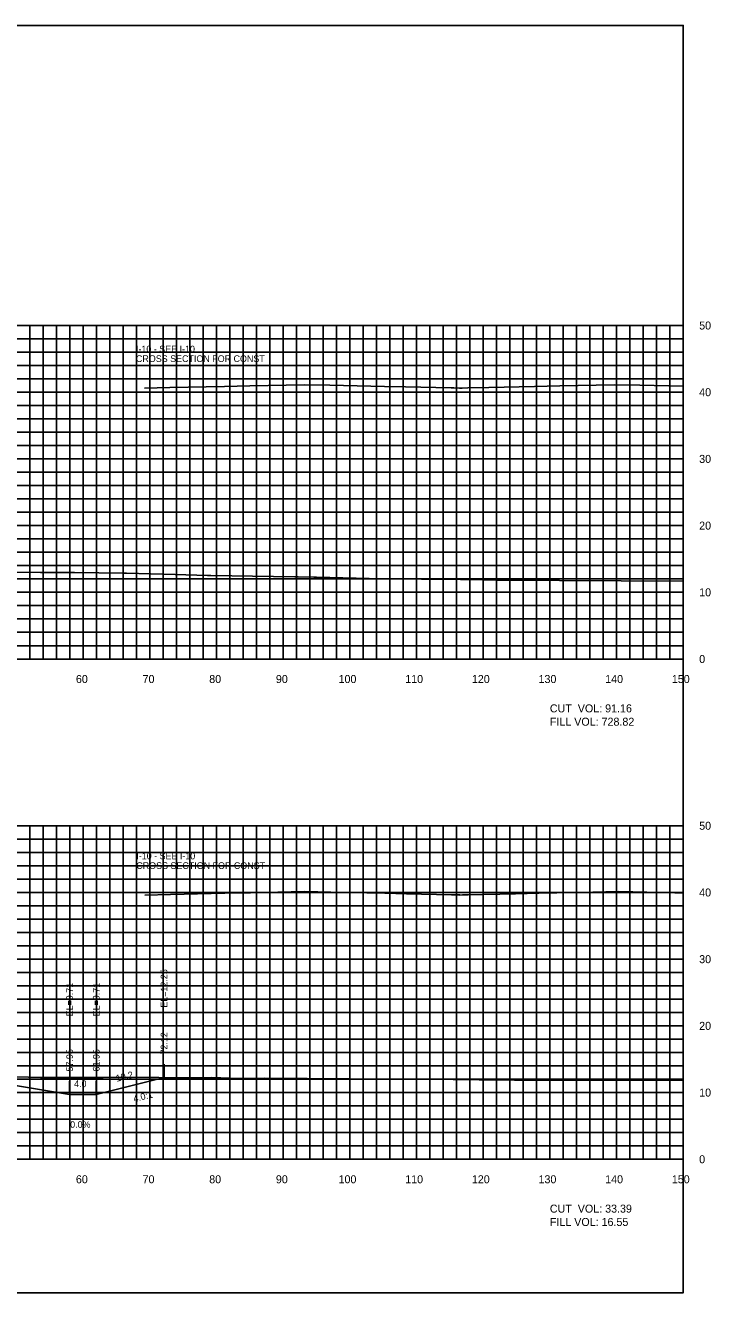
# Model space of a CAD drawing. Extents: x 1797714 to 1804825, y 249015 to 250269.
# Drawn here: x 1802682.3 to 1802785.1, y 250079.4 to 250269.4 of the extents above; entities that cross this region are included whole.
import ezdxf

# ---------------------------------------------------------------- set-up
doc = ezdxf.new("R2010")
doc.units = 0
for name, color, linetype in [('10', 7, 'Continuous'), ('3', 7, 'Continuous'), ('31', 7, 'Continuous'), ('4', 7, 'Continuous'), ('60', 7, 'Continuous'), ('ANNO-TXT', 7, 'Continuous'), ('CL-CNST', 7, 'Continuous'), ('Level 62', 7, 'Continuous'), ('M-ROADS', 7, 'Continuous')]:
    doc.layers.add(name, color=color, linetype=linetype)

msp = doc.modelspace()

# ---------------------------------------------------------------- linework, layer by layer
for p, q in [((1802703.12, 250111.68), (1802703.12, 250113.68)), ((1802688.95, 250109.14), (1802688.95, 250111.14)), ((1802692.95, 250109.14), (1802692.95, 250111.14))]:
    msp.add_line(p, q)
msp.add_lwpolyline([(1802481, 250079.43), (1802781, 250079.43), (1802781, 250269.43), (1802481, 250269.43)], close=True)
at = {"layer": '60'}
for p, q in [((1802781, 250174.43), (1802781, 250224.43)), ((1802781.06, 250224.43), (1802781, 250224.43)), ((1802781.06, 250214.43), (1802781, 250214.43)), ((1802781.06, 250204.43), (1802781, 250204.43)), ((1802781.06, 250194.43), (1802781, 250194.43)), ((1802781.06, 250184.43), (1802781, 250184.43)), ((1802481, 250174.43), (1802781, 250174.43)), ((1802691, 250174.37), (1802691, 250174.43)), ((1802701, 250174.37), (1802701, 250174.43)), ((1802711, 250174.37), (1802711, 250174.43)), ((1802721, 250174.37), (1802721, 250174.43)), ((1802731, 250174.37), (1802731, 250174.43)), ((1802741, 250174.37), (1802741, 250174.43)), ((1802751, 250174.37), (1802751, 250174.43)), ((1802761, 250174.37), (1802761, 250174.43)), ((1802771, 250174.37), (1802771, 250174.43)), ((1802781, 250174.37), (1802781, 250174.43)), ((1802781.06, 250174.43), (1802781, 250174.43)), ((1802781, 250099.43), (1802781, 250149.43)), ((1802781.06, 250149.43), (1802781, 250149.43)), ((1802781.06, 250139.43), (1802781, 250139.43)), ((1802781.06, 250129.43), (1802781, 250129.43)), ((1802781.06, 250119.43), (1802781, 250119.43)), ((1802781.06, 250109.43), (1802781, 250109.43)), ((1802481, 250099.43), (1802781, 250099.43)), ((1802691, 250099.37), (1802691, 250099.43)), ((1802701, 250099.37), (1802701, 250099.43)), ((1802711, 250099.37), (1802711, 250099.43)), ((1802721, 250099.37), (1802721, 250099.43)), ((1802731, 250099.37), (1802731, 250099.43)), ((1802741, 250099.37), (1802741, 250099.43)), ((1802751, 250099.37), (1802751, 250099.43)), ((1802761, 250099.37), (1802761, 250099.43)), ((1802771, 250099.37), (1802771, 250099.43)), ((1802781, 250099.37), (1802781, 250099.43)), ((1802781.06, 250099.43), (1802781, 250099.43))]:
    msp.add_line(p, q, dxfattribs=at)
at = {"layer": 'CL-CNST'}
for points in [[(1802700.2, 250215.03), (1802703.98, 250215.12), (1802712.2, 250215.3), (1802715.98, 250215.38), (1802724.2, 250215.56), (1802727.98, 250215.48), (1802736.2, 250215.3), (1802739.35, 250215.23), (1802746.2, 250215.08), (1802746.6, 250215.07), (1802747.45, 250215.05), (1802747.45, 250215.05), (1802747.45, 250215.05), (1802747.85, 250215.06), (1802748.7, 250215.08), (1802751.86, 250215.15), (1802758.7, 250215.3), (1802762.49, 250215.38), (1802770.7, 250215.56), (1802774.49, 250215.48), (1802781, 250215.33)], [(1802700.25, 250139.03), (1802704.11, 250139.12), (1802712.25, 250139.3), (1802716.11, 250139.38), (1802724.25, 250139.56), (1802728.12, 250139.48), (1802736.25, 250139.3), (1802739.47, 250139.23), (1802746.25, 250139.08), (1802746.65, 250139.07), (1802747.49, 250139.05), (1802747.49, 250139.05), (1802747.5, 250139.04), (1802747.9, 250139.05), (1802748.75, 250139.07), (1802755.83, 250139.22), (1802759.33, 250139.3), (1802767.45, 250139.48), (1802771.33, 250139.56), (1802779.76, 250139.38), (1802781, 250139.35)], [(1802608.84, 250113.01), (1802618.84, 250113.41), (1802631, 250113.63), (1802658, 250113.04), (1802662, 250112.88), (1802667.95, 250112.64), (1802688.95, 250109.14), (1802692.95, 250109.14), (1802703.12, 250111.68)]]:
    msp.add_lwpolyline(points, dxfattribs=at)
at = {"layer": 'Level 62'}
for p, q in [((1802481, 250224.43), (1802781, 250224.43)), ((1802683, 250174.43), (1802683, 250224.43)), ((1802685, 250174.43), (1802685, 250224.43)), ((1802687, 250174.43), (1802687, 250224.43)), ((1802689, 250174.43), (1802689, 250224.43)), ((1802691, 250174.43), (1802691, 250224.43)), ((1802693, 250174.43), (1802693, 250224.43)), ((1802695, 250174.43), (1802695, 250224.43)), ((1802697, 250174.43), (1802697, 250224.43)), ((1802699, 250174.43), (1802699, 250224.43)), ((1802701, 250174.43), (1802701, 250224.43)), ((1802703, 250174.43), (1802703, 250224.43)), ((1802705, 250174.43), (1802705, 250224.43)), ((1802707, 250174.43), (1802707, 250224.43)), ((1802709, 250174.43), (1802709, 250224.43)), ((1802711, 250174.43), (1802711, 250224.43)), ((1802713, 250174.43), (1802713, 250224.43)), ((1802715, 250174.43), (1802715, 250224.43)), ((1802717, 250174.43), (1802717, 250224.43)), ((1802719, 250174.43), (1802719, 250224.43)), ((1802721, 250174.43), (1802721, 250224.43)), ((1802723, 250174.43), (1802723, 250224.43)), ((1802725, 250174.43), (1802725, 250224.43)), ((1802727, 250174.43), (1802727, 250224.43)), ((1802729, 250174.43), (1802729, 250224.43)), ((1802731, 250174.43), (1802731, 250224.43)), ((1802733, 250174.43), (1802733, 250224.43)), ((1802735, 250174.43), (1802735, 250224.43)), ((1802737, 250174.43), (1802737, 250224.43)), ((1802739, 250174.43), (1802739, 250224.43)), ((1802741, 250174.43), (1802741, 250224.43)), ((1802743, 250174.43), (1802743, 250224.43)), ((1802745, 250174.43), (1802745, 250224.43)), ((1802747, 250174.43), (1802747, 250224.43)), ((1802749, 250174.43), (1802749, 250224.43)), ((1802751, 250174.43), (1802751, 250224.43)), ((1802753, 250174.43), (1802753, 250224.43)), ((1802755, 250174.43), (1802755, 250224.43)), ((1802757, 250174.43), (1802757, 250224.43)), ((1802759, 250174.43), (1802759, 250224.43)), ((1802761, 250174.43), (1802761, 250224.43)), ((1802763, 250174.43), (1802763, 250224.43)), ((1802765, 250174.43), (1802765, 250224.43)), ((1802767, 250174.43), (1802767, 250224.43)), ((1802769, 250174.43), (1802769, 250224.43)), ((1802771, 250174.43), (1802771, 250224.43)), ((1802773, 250174.43), (1802773, 250224.43)), ((1802775, 250174.43), (1802775, 250224.43)), ((1802777, 250174.43), (1802777, 250224.43)), ((1802779, 250174.43), (1802779, 250224.43)), ((1802781, 250174.43), (1802781, 250224.43)), ((1802481, 250222.43), (1802781, 250222.43)), ((1802481, 250220.43), (1802781, 250220.43)), ((1802481, 250218.43), (1802781, 250218.43)), ((1802481, 250216.43), (1802781, 250216.43)), ((1802481, 250214.43), (1802781, 250214.43)), ((1802481, 250212.43), (1802781, 250212.43)), ((1802481, 250210.43), (1802781, 250210.43)), ((1802481, 250208.43), (1802781, 250208.43)), ((1802481, 250206.43), (1802781, 250206.43)), ((1802481, 250204.43), (1802781, 250204.43)), ((1802481, 250202.43), (1802781, 250202.43)), ((1802481, 250200.43), (1802781, 250200.43)), ((1802481, 250198.43), (1802781, 250198.43)), ((1802481, 250196.43), (1802781, 250196.43)), ((1802481, 250194.43), (1802781, 250194.43)), ((1802481, 250192.43), (1802781, 250192.43)), ((1802481, 250190.43), (1802781, 250190.43)), ((1802481, 250188.43), (1802781, 250188.43)), ((1802481, 250186.43), (1802781, 250186.43)), ((1802481, 250184.43), (1802781, 250184.43)), ((1802481, 250182.43), (1802781, 250182.43)), ((1802481, 250180.43), (1802781, 250180.43)), ((1802481, 250178.43), (1802781, 250178.43)), ((1802481, 250176.43), (1802781, 250176.43)), ((1802481, 250174.43), (1802781, 250174.43)), ((1802481, 250149.43), (1802781, 250149.43)), ((1802683, 250099.43), (1802683, 250149.43)), ((1802685, 250099.43), (1802685, 250149.43)), ((1802687, 250099.43), (1802687, 250149.43)), ((1802689, 250099.43), (1802689, 250149.43)), ((1802691, 250099.43), (1802691, 250149.43)), ((1802693, 250099.43), (1802693, 250149.43)), ((1802695, 250099.43), (1802695, 250149.43)), ((1802697, 250099.43), (1802697, 250149.43)), ((1802699, 250099.43), (1802699, 250149.43)), ((1802701, 250099.43), (1802701, 250149.43)), ((1802703, 250099.43), (1802703, 250149.43)), ((1802705, 250099.43), (1802705, 250149.43)), ((1802707, 250099.43), (1802707, 250149.43)), ((1802709, 250099.43), (1802709, 250149.43)), ((1802711, 250099.43), (1802711, 250149.43)), ((1802713, 250099.43), (1802713, 250149.43)), ((1802715, 250099.43), (1802715, 250149.43)), ((1802717, 250099.43), (1802717, 250149.43)), ((1802719, 250099.43), (1802719, 250149.43)), ((1802721, 250099.43), (1802721, 250149.43)), ((1802723, 250099.43), (1802723, 250149.43)), ((1802725, 250099.43), (1802725, 250149.43)), ((1802727, 250099.43), (1802727, 250149.43)), ((1802729, 250099.43), (1802729, 250149.43)), ((1802731, 250099.43), (1802731, 250149.43)), ((1802733, 250099.43), (1802733, 250149.43)), ((1802735, 250099.43), (1802735, 250149.43)), ((1802737, 250099.43), (1802737, 250149.43)), ((1802739, 250099.43), (1802739, 250149.43)), ((1802741, 250099.43), (1802741, 250149.43)), ((1802743, 250099.43), (1802743, 250149.43)), ((1802745, 250099.43), (1802745, 250149.43)), ((1802747, 250099.43), (1802747, 250149.43)), ((1802749, 250099.43), (1802749, 250149.43)), ((1802751, 250099.43), (1802751, 250149.43)), ((1802753, 250099.43), (1802753, 250149.43)), ((1802755, 250099.43), (1802755, 250149.43)), ((1802757, 250099.43), (1802757, 250149.43)), ((1802759, 250099.43), (1802759, 250149.43)), ((1802761, 250099.43), (1802761, 250149.43)), ((1802763, 250099.43), (1802763, 250149.43)), ((1802765, 250099.43), (1802765, 250149.43)), ((1802767, 250099.43), (1802767, 250149.43)), ((1802769, 250099.43), (1802769, 250149.43)), ((1802771, 250099.43), (1802771, 250149.43)), ((1802773, 250099.43), (1802773, 250149.43)), ((1802775, 250099.43), (1802775, 250149.43)), ((1802777, 250099.43), (1802777, 250149.43)), ((1802779, 250099.43), (1802779, 250149.43)), ((1802781, 250099.43), (1802781, 250149.43)), ((1802481, 250147.43), (1802781, 250147.43)), ((1802481, 250145.43), (1802781, 250145.43)), ((1802481, 250143.43), (1802781, 250143.43)), ((1802481, 250141.43), (1802781, 250141.43)), ((1802481, 250139.43), (1802781, 250139.43)), ((1802481, 250137.43), (1802781, 250137.43)), ((1802481, 250135.43), (1802781, 250135.43)), ((1802481, 250133.43), (1802781, 250133.43)), ((1802481, 250131.43), (1802781, 250131.43)), ((1802481, 250129.43), (1802781, 250129.43)), ((1802481, 250127.43), (1802781, 250127.43)), ((1802481, 250125.43), (1802781, 250125.43)), ((1802481, 250123.43), (1802781, 250123.43)), ((1802481, 250121.43), (1802781, 250121.43)), ((1802481, 250119.43), (1802781, 250119.43)), ((1802481, 250117.43), (1802781, 250117.43)), ((1802481, 250115.43), (1802781, 250115.43)), ((1802481, 250113.43), (1802781, 250113.43)), ((1802481, 250111.43), (1802781, 250111.43)), ((1802481, 250109.43), (1802781, 250109.43)), ((1802481, 250107.43), (1802781, 250107.43)), ((1802481, 250105.43), (1802781, 250105.43)), ((1802481, 250103.43), (1802781, 250103.43)), ((1802481, 250101.43), (1802781, 250101.43)), ((1802481, 250099.43), (1802781, 250099.43))]:
    msp.add_line(p, q, dxfattribs=at)
at = {"layer": 'M-ROADS'}
for points in [[(1802680.54, 250187.46), (1802684.6, 250187.42), (1802684.75, 250187.42), (1802685.11, 250187.42), (1802689.71, 250187.38), (1802697.01, 250187.28), (1802697.25, 250187.28), (1802697.51, 250187.28), (1802704.77, 250187.11), (1802709.63, 250186.97), (1802709.83, 250186.97), (1802710.14, 250186.97), (1802719.56, 250186.82), (1802722.75, 250186.75), (1802723.16, 250186.75), (1802723.26, 250186.75), (1802725.61, 250186.7), (1802726.01, 250186.69), (1802735.87, 250186.47), (1802747.6, 250186.34), (1802747.61, 250186.34), (1802747.89, 250186.34), (1802747.9, 250186.34), (1802748.4, 250186.34), (1802748.5, 250186.34), (1802748.51, 250186.34), (1802748.77, 250186.33), (1802753.14, 250186.26), (1802781, 250186.11)], [(1802677.38, 250111.87), (1802684.57, 250111.68), (1802685.34, 250111.67), (1802687.23, 250111.7), (1802687.48, 250111.7), (1802694, 250111.7), (1802697.02, 250111.73), (1802702.33, 250111.7), (1802705.54, 250111.65), (1802710.21, 250111.71), (1802711.63, 250111.64), (1802714.06, 250111.55), (1802715.24, 250111.56), (1802718.17, 250111.58), (1802731.01, 250111.5), (1802735.58, 250111.44), (1802736.03, 250111.44), (1802736.16, 250111.44), (1802736.78, 250111.44), (1802739.4, 250111.45), (1802746.51, 250111.38), (1802750.37, 250111.33), (1802751.86, 250111.34), (1802753.22, 250111.34), (1802753.51, 250111.34), (1802754.5, 250111.34), (1802755.69, 250111.31), (1802756.79, 250111.29), (1802768.7, 250111.31), (1802781, 250111.31)]]:
    msp.add_lwpolyline(points, dxfattribs=at)

# ---------------------------------------------------------------- texts
msp.add_text('4.0:1', height=1, rotation=14.0362).set_placement((1802698.64, 250107.99))
at = {"layer": '10'}
for s, p in [('60', (1802689.9, 250170.83)), ('70', (1802699.9, 250170.83)), ('80', (1802709.9, 250170.83)), ('90', (1802719.9, 250170.83)), ('100', (1802729.3, 250170.83)), ('110', (1802739.3, 250170.83)), ('120', (1802749.3, 250170.83)), ('130', (1802759.3, 250170.83)), ('140', (1802769.3, 250170.83)), ('150', (1802779.3, 250170.83)), ('60', (1802689.9, 250095.83)), ('70', (1802699.9, 250095.83)), ('80', (1802709.9, 250095.83)), ('90', (1802719.9, 250095.83)), ('100', (1802729.3, 250095.83)), ('110', (1802739.3, 250095.83)), ('120', (1802749.3, 250095.83)), ('130', (1802759.3, 250095.83)), ('140', (1802769.3, 250095.83)), ('150', (1802779.3, 250095.83))]:
    msp.add_text(s, height=1.2, dxfattribs=at).set_placement(p)
at = {"layer": '3'}
for s, p in [('I-10 - SEE I-10 ', (1802698.91, 250220.4)), ('CROSS SECTION FOR CONST ', (1802698.91, 250218.96)), ('I-10 - SEE I-10 ', (1802698.96, 250144.4)), ('CROSS SECTION FOR CONST ', (1802698.96, 250142.96))]:
    msp.add_text(s, height=1, dxfattribs=at).set_placement(p)
for s, p in [('EL=12.25', (1802703.62, 250122.16)), ('EL=9.71', (1802689.45, 250120.86)), ('EL=9.71', (1802693.45, 250120.86)), ('72.12', (1802703.62, 250115.13)), ('57.95', (1802689.45, 250112.59)), ('61.95', (1802693.45, 250112.59))]:
    msp.add_text(s, height=1, rotation=90, dxfattribs=at).set_placement(p)
at = {"layer": '31'}
for s, p in [('50', (1802783.4, 250223.83)), ('40', (1802783.4, 250213.83)), ('30', (1802783.4, 250203.83)), ('20', (1802783.4, 250193.83)), ('10', (1802783.4, 250183.83)), ('0', (1802783.4, 250173.83)), ('50', (1802783.4, 250148.83)), ('40', (1802783.4, 250138.83)), ('30', (1802783.4, 250128.83)), ('20', (1802783.4, 250118.83)), ('10', (1802783.4, 250108.83)), ('0', (1802783.4, 250098.83))]:
    msp.add_text(s, height=1.2, dxfattribs=at).set_placement(p)
at = {"layer": '4'}
msp.add_text('10.2', height=1, rotation=14.0362, dxfattribs=at).set_placement((1802696.04, 250111.05))
for s, p in [('4.0', (1802689.63, 250110.24)), ('0.0%', (1802689.04, 250104.14))]:
    msp.add_text(s, height=1, dxfattribs=at).set_placement(p)
at = {"layer": 'ANNO-TXT'}
for s, p in [('CUT  VOL: 91.16', (1802761, 250166.43)), ('FILL VOL: 728.82', (1802761, 250164.43)), ('CUT  VOL: 33.39', (1802761, 250091.43)), ('FILL VOL: 16.55', (1802761, 250089.43))]:
    msp.add_text(s, height=1.2, dxfattribs=at).set_placement(p)

doc.saveas('drawing.dxf')
